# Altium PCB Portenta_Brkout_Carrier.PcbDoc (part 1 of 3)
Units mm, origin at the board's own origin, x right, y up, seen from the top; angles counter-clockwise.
Board outline 163.96 x 72.14 mm, 4 copper layers (Top, GND, PWR, Bottom), stack 1.612 mm thick; 71 components, 171 nets, 700 pads, 387 vias.
Unrouted connection lines stored in the file: 2.
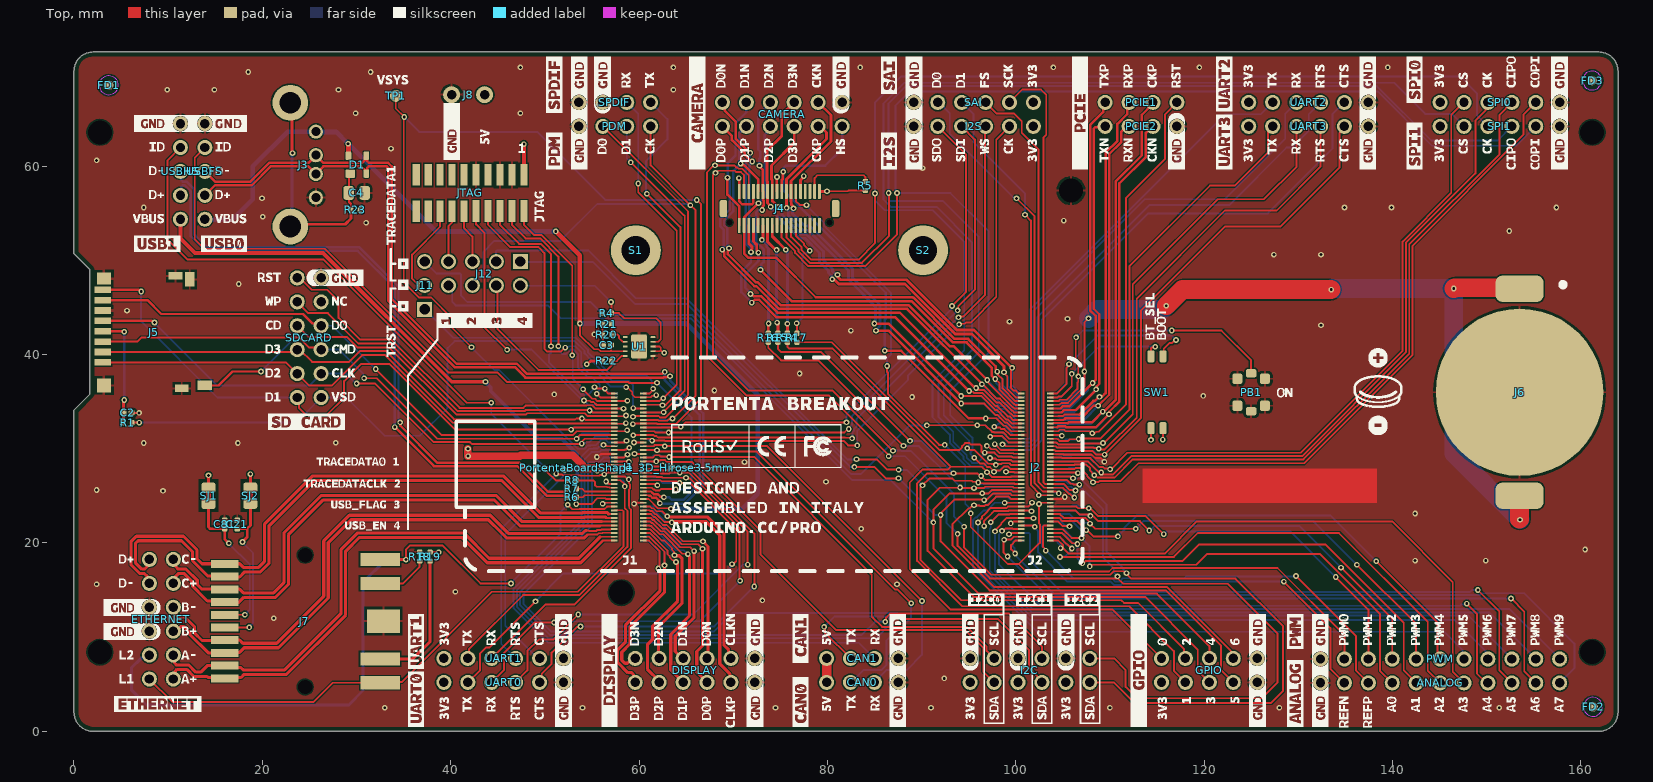
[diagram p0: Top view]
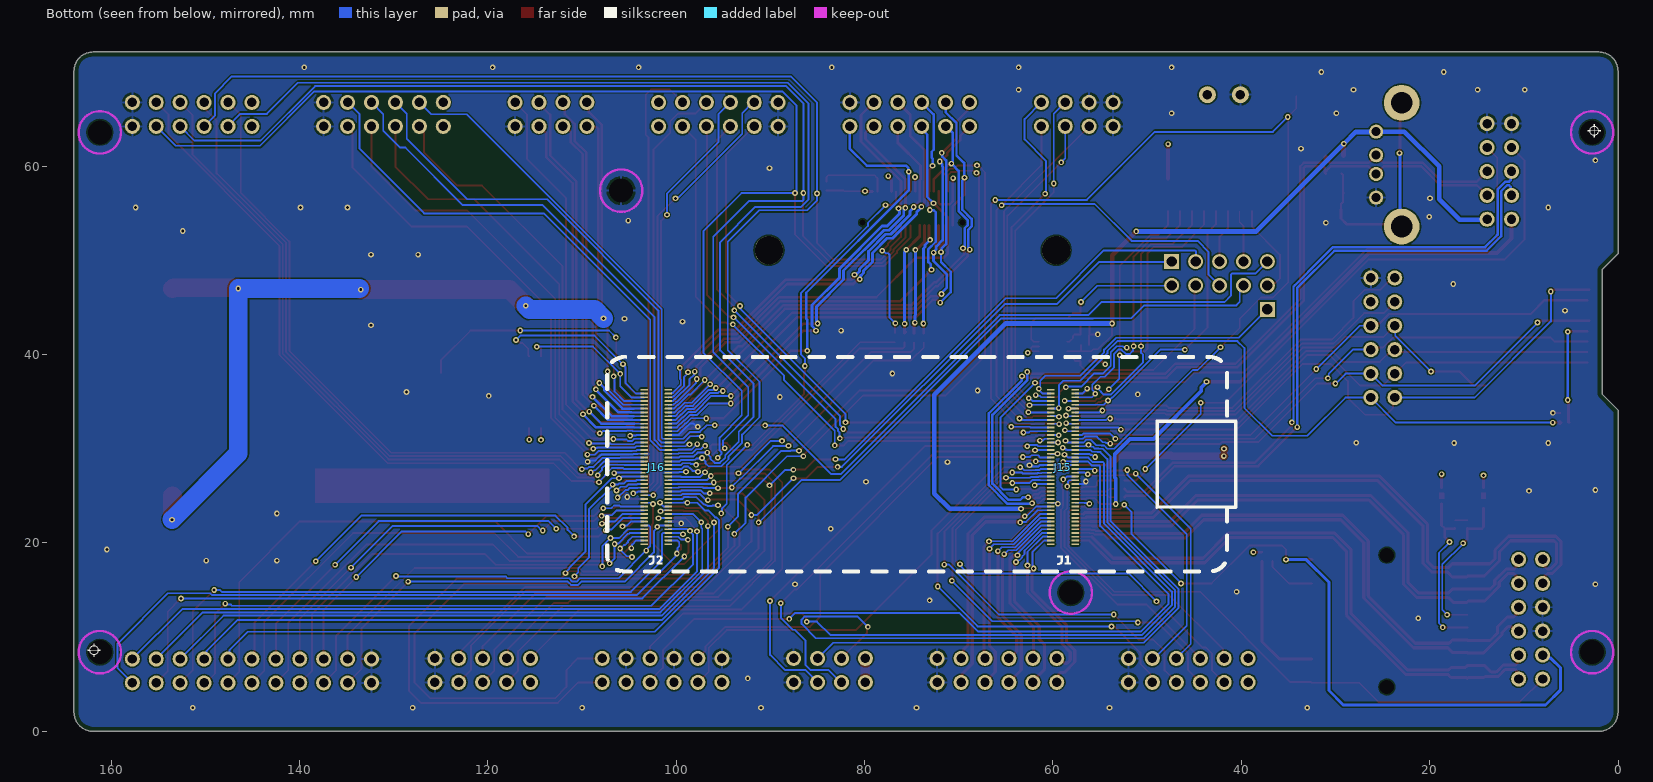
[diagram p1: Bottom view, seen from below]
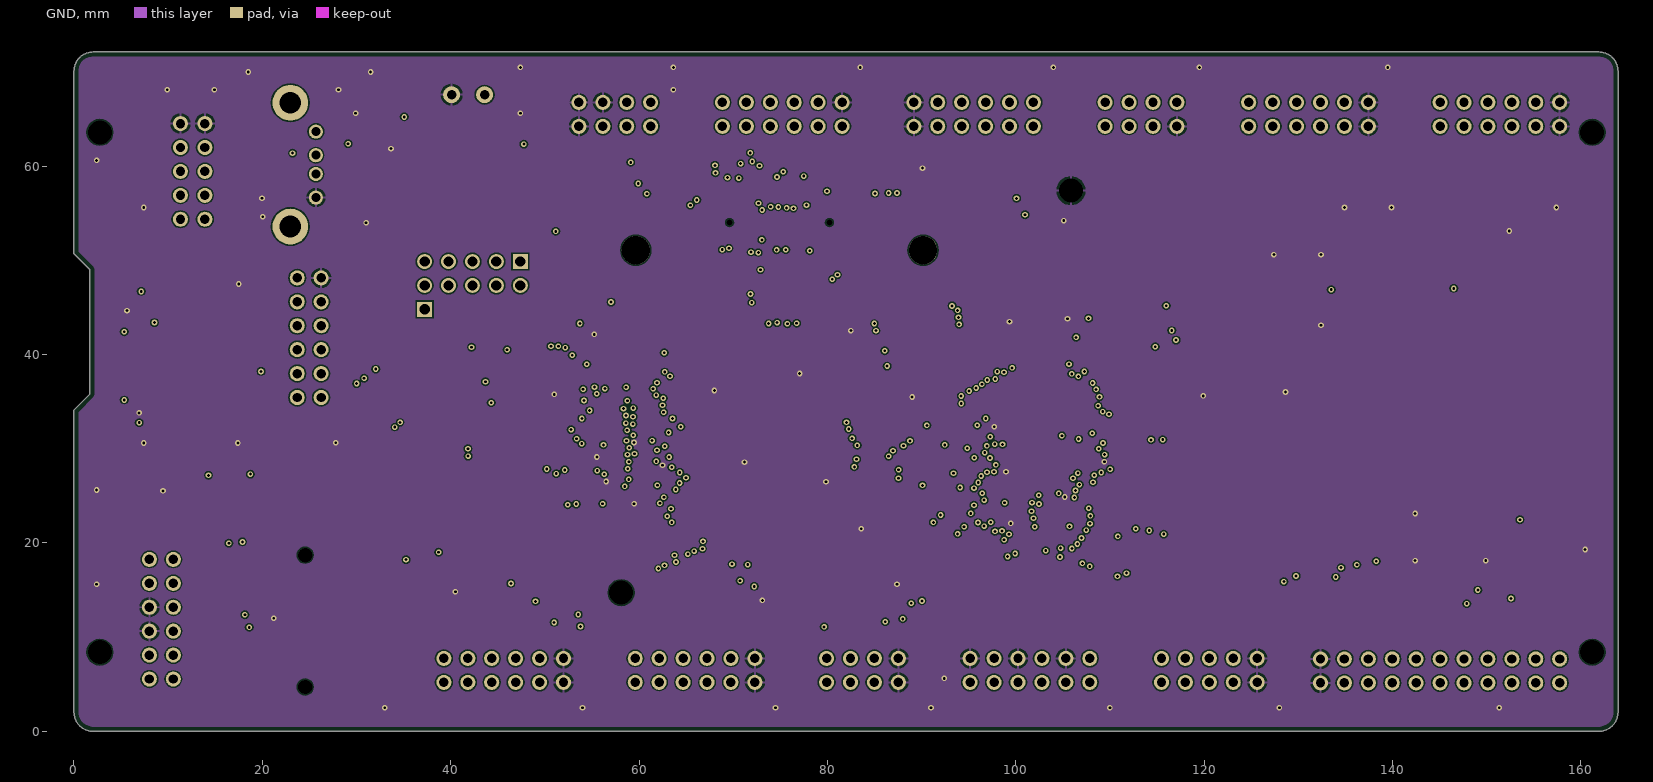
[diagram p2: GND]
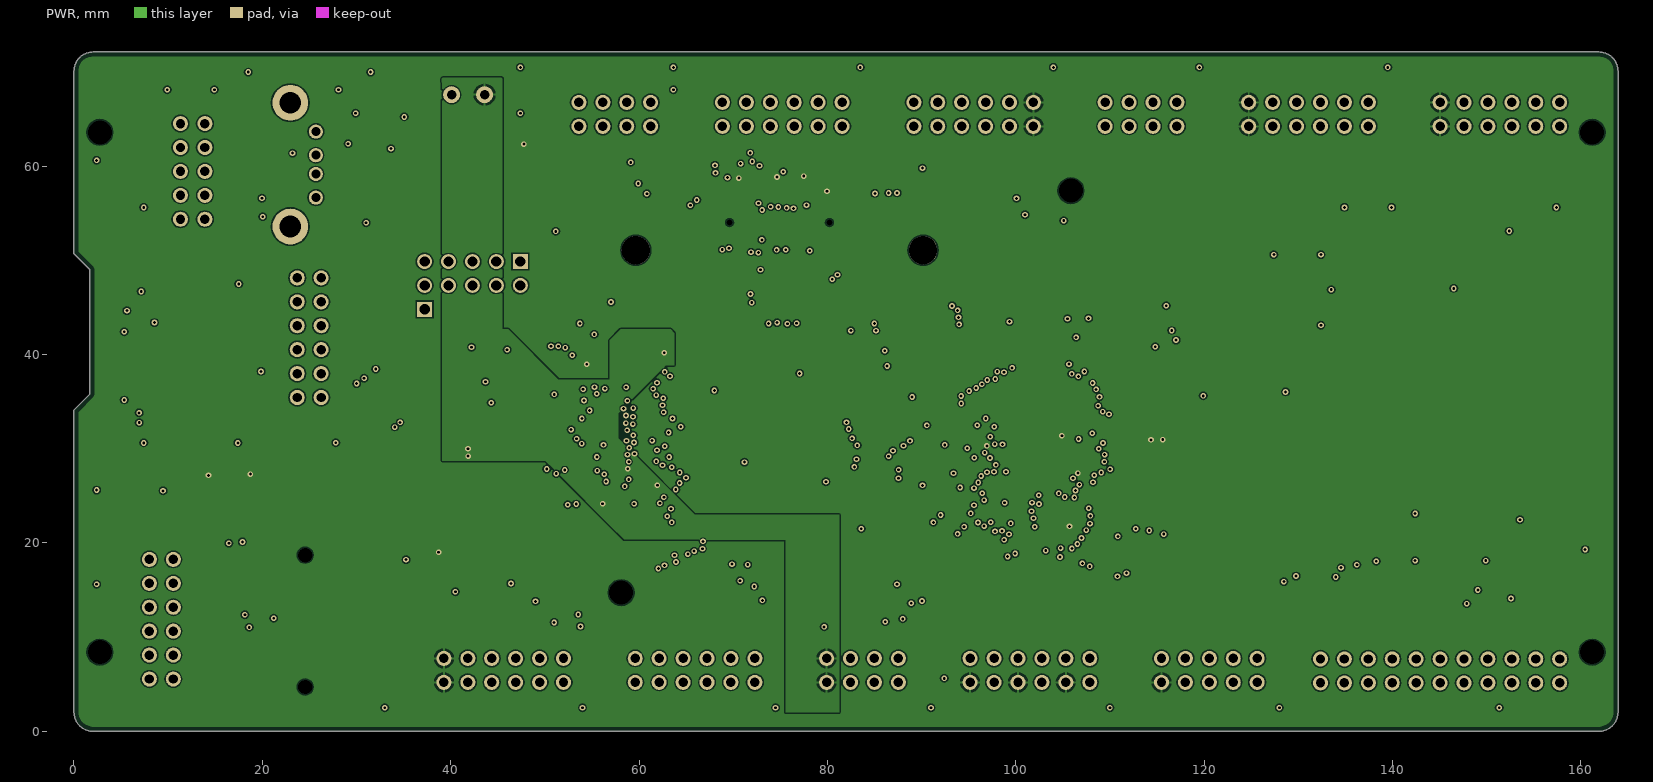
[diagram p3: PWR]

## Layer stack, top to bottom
Top Solder: solder mask 0.0102, Solder Resist, Dk 3.5
Top: signal copper 0.035
Dielectric 1: prepreg 0.356, FR-4, Dk 4.1
GND: signal copper 0.035
Dielectric3: core 0.76, FR-4, Dk 4.8
PWR: signal copper 0.035
Dielectric2: prepreg 0.356, FR-4, Dk 4.1
Bottom: signal copper 0.035
Bottom Solder: solder mask 0.0102, Solder Resist, Dk 3.5

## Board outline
0,2.032 0,34.11 1.7,35.81 1.7,49 0,50.7 0,70.104 cw(c2.032,70.104) 2.032,72.136 2.058,72.136 161.925,72.136 cw(c161.925,70.104) 163.957,70.104 163.957,70.078 163.957,2.032 cw(c161.925,2.032) 161.925,0 2.032,0 cw(c2.032,2.032)

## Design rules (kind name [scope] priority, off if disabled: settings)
BoardOutlineClearance mousebites [(ObjectKind = 'Pad') And (Name = 'Free-MOUSEBITES')] p1: gap=0 ignorepadtopadclearanceinfootprint=FALSE
BoardOutlineClearance [All] p2: gap=0.5 ignorepadtopadclearanceinfootprint=FALSE
Clearance Clearance_Diff [InAnyDifferentialPair] p1: gap=0.127 ignorepadtopadclearanceinfootprint=TRUE
Clearance [All] p2: gap=0.15 ignorepadtopadclearanceinfootprint=TRUE
DiffPairsRouting DiffPairsRouting_CAM [All] p1 off: maxlimit=0.254 minlimit=0.127 mostfreqgap=0.254 toplayer_prefgap=0.15 toplayer_minwidth=0.264 toplayer_maxwidth=0.381 toplayer_prefwidth=0.33 bottomlayer_prefgap=0.15 bottomlayer_minwidth=0.264 bottomlayer_maxwidth=0.381 bottomlayer_prefwidth=0.328 impedanceprofiledriven=TRUE impedanceprofileid={37DED0B3-47C4-494E-94CB-F43A59EAE40C} impedanceprofilevalue=100.000000 maxuncoupledlength=12.7
DiffPairsRouting DiffPairsRouting_DISPLAY [InDifferentialPairClass('DSI')] p2 off: maxlimit=0.254 minlimit=0.15 mostfreqgap=0.254 toplayer_prefgap=0.15 toplayer_minwidth=0.328 toplayer_maxwidth=0.381 toplayer_prefwidth=0.33 bottomlayer_prefgap=0.15 bottomlayer_minwidth=0.328 bottomlayer_maxwidth=0.381 bottomlayer_prefwidth=0.328 impedanceprofiledriven=TRUE impedanceprofileid={37DED0B3-47C4-494E-94CB-F43A59EAE40C} impedanceprofilevalue=100.000000 maxuncoupledlength=12.7
DiffPairsRouting DiffPairsRouting_USB [InDifferentialPairClass('USB')] p3: maxlimit=0.254 minlimit=0.127 mostfreqgap=0.254 toplayer_maxgap=0.127 toplayer_prefgap=0.127 toplayer_minwidth=0.2 toplayer_maxwidth=0.264 toplayer_prefwidth=0.264 bottomlayer_maxgap=0.127 bottomlayer_prefgap=0.127 bottomlayer_minwidth=0.264 bottomlayer_maxwidth=0.264 bottomlayer_prefwidth=0.264 impedanceprofiledriven=TRUE impedanceprofileid={A94ECF99-AB87-4BDF-9033-C085802CB064} impedanceprofilevalue=90.000000 maxuncoupledlength=12.7
DiffPairsRouting DiffPairsRouting_ETH [InDifferentialPairClass('ETH')] p4: maxlimit=0.254 minlimit=0.15 mostfreqgap=0.254 toplayer_maxgap=0.15 toplayer_prefgap=0.15 toplayer_minwidth=0.328 toplayer_maxwidth=0.33 toplayer_prefwidth=0.33 bottomlayer_maxgap=0.15 bottomlayer_prefgap=0.15 bottomlayer_minwidth=0.328 bottomlayer_maxwidth=0.328 bottomlayer_prefwidth=0.328 impedanceprofiledriven=TRUE impedanceprofileid={37DED0B3-47C4-494E-94CB-F43A59EAE40C} impedanceprofilevalue=100.000000 maxuncoupledlength=12.7
DiffPairsRouting DiffPairsRouting_PCIE [InDifferentialPairClass('PCIE')] p5: maxlimit=0.254 minlimit=0.127 mostfreqgap=0.254 toplayer_prefgap=0.127 toplayer_minwidth=0.264 toplayer_maxwidth=0.381 toplayer_prefwidth=0.264 bottomlayer_prefgap=0.127 bottomlayer_minwidth=0.264 bottomlayer_maxwidth=0.381 bottomlayer_prefwidth=0.264 impedanceprofiledriven=TRUE impedanceprofileid={A94ECF99-AB87-4BDF-9033-C085802CB064} impedanceprofilevalue=90.000000 maxuncoupledlength=12.7
HoleSize [All] p1: absolutevalues=TRUE maxlimit=5 minlimit=0.025 maxpercent=80.000 minpercent=20.000
MinimumSolderMaskSliver [All] p1 off: minsoldermaskwidth=0.254
PolygonConnect [All] p1: thpad.connectstyle=Relief thpad.reliefconductorwidth=0.254 thpad.reliefentries=4 thpad.polygonreliefangle="90 Angle" thpad.airgapwidth=0.254 smdpad.connectstyle=Relief smdpad.reliefconductorwidth=0.254 smdpad.reliefentries=4 smdpad.polygonreliefangle="90 Angle" smdpad.airgapwidth=0.254 via.connectstyle=Direct via.reliefconductorwidth=0.254 via.reliefentries=4 via.polygonreliefangle="90 Angle" via.airgapwidth=0.254
RoomDefinition "HDConnectors MALE" [InComponentClass('HDConnectors MALE')] p1 off: confinementstyle=ConfineIn formatcopy=TRUE lockcomponents=FALSE outline 165.1,0.381 173.99,0.381 173.99,20.193 165.1,20.193
RoomDefinition USB [InComponentClass('USB')] p2 off: confinementstyle=ConfineIn formatcopy=TRUE lockcomponents=FALSE outline 165.1,145.542 179.451,145.542 179.451,157.099 165.1,157.099
RoomDefinition U_ETHERNET [InComponentClass('U_ETHERNET')] p3 off: confinementstyle=ConfineIn formatcopy=TRUE lockcomponents=FALSE outline 165.1,119.761 217.551,119.761 217.551,145.415 165.1,145.415
RoomDefinition TOP [InComponentClass('TOP')] p4 off: confinementstyle=ConfineIn formatcopy=TRUE lockcomponents=FALSE outline 165.1,87.757 416.56,87.757 416.56,118.364 165.1,118.364
RoomDefinition SD [InComponentClass('SD')] p5 off: confinementstyle=ConfineIn formatcopy=TRUE lockcomponents=FALSE outline 165.1,69.977 197.485,69.977 197.485,87.63 165.1,87.63
RoomDefinition "HDConnectors FEMALE" [InComponentClass('HDConnectors FEMALE')] p6 off: confinementstyle=ConfineIn formatcopy=TRUE lockcomponents=FALSE outline 165.1,0.127 196.596,0.127 196.596,68.707 165.1,68.707
RoutingLayers [All] p1: top layer_v5=TRUE mid layer 1_v5=FALSE mid layer 2_v5=FALSE bottom layer_v5=TRUE
RoutingVias [All] p1: holewidth=0.3 width=0.6 viastyle="Through Hole" minholewidth=0.15 minwidth=0.3 maxholewidth=0.711 maxwidth=1.27
SMDEntry [All] p1: side=TRUE corner=FALSE anyangle=FALSE
SMDNeckDown [All] p1 off: percent=10.000
SolderMaskExpansion VIA [IsVia] p1: expansion=0.102 istentingtop=TRUE
SolderMaskExpansion [All] p2: expansion=0.1 istentingtop=FALSE
Width [All] p1: maxlimit=2 minlimit=0.127 preferedwidth=0.2
26 further rules are at their usual default settings.

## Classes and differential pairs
net class USB: D_1_N D_1_P
differential pair class USB: D_1 USB_FS.D_1 USB_HS.D_1
differential pair class PCIE: PCIE.CK_1 PCIE.RX_1 PCIE.TX_1
differential pair class ETH: ETH.A_1 ETH.B_1 ETH.C_1 ETH.D_1
differential pair class DSI: DISPLAY.CLK_1 DISPLAY.D0_1 DISPLAY.D1_1 DISPLAY.D2_1 DISPLAY.D3_1
differential pair class CAM: CAM.CK_1 CAM.D0_1 CAM.D1_1 CAM.D2_1 CAM.D3_1
component class "HDConnectors MALE": 2 J15 J16
component class USB: C3 C4 D1 J3 R4 R20 R21 R22 R23 U1
component class U_ETHERNET: C21 C81 J7 R18 R19 SJ1 SJ2
component class TOP: ANALOG CAMERA CAN0 CAN1 DISPLAY ETHERNET FD1 FD2 FD3 GPIO I2C I2S J4 J6 J8 J11 J12 JTAG PB1 PCIE1 PCIE2 PDM PWM R5 R6 R7 R8 R14 R15 R16 R17 S1 S2 SAI SDCARD SPDIF SPI0 SPI1 SW1 TP1 UART0 UART1 UART2 UART3 USBFS USBHS
component class SD: C2 J5 R1
component class "HDConnectors FEMALE": J1 J2 PortentaBoardShape_3D_Hirose3.5mm
differential pair D_1: +D_1_P -D_1_N
differential pair USB_HS.D_1: +USB_HS.D_1_P -USB_HS.D_1_N
differential pair USB_FS.D_1: +USB_FS.D_1_P -USB_FS.D_1_N
differential pair PCIE.TX_1: +PCIE.TX_1_P -PCIE.TX_1_N
differential pair PCIE.RX_1: +PCIE.RX_1_P -PCIE.RX_1_N
differential pair PCIE.CK_1: +PCIE.CK_1_P -PCIE.CK_1_N
differential pair ETH.D_1: +ETH.D_1_P -ETH.D_1_N
differential pair ETH.C_1: +ETH.C_1_P -ETH.C_1_N
differential pair ETH.B_1: +ETH.B_1_P -ETH.B_1_N
differential pair ETH.A_1: +ETH.A_1_P -ETH.A_1_N
differential pair DISPLAY.D3_1: +DISPLAY.D3_1_P -DISPLAY.D3_1_N
differential pair DISPLAY.D2_1: +DISPLAY.D2_1_P -DISPLAY.D2_1_N
differential pair DISPLAY.D1_1: +DISPLAY.D1_1_P -DISPLAY.D1_1_N
differential pair DISPLAY.D0_1: +DISPLAY.D0_1_P -DISPLAY.D0_1_N
differential pair DISPLAY.CLK_1: +DISPLAY.CLK_1_P -DISPLAY.CLK_1_N
differential pair CAM.D3_1: +CAM.D3_1_P -CAM.D3_1_N
differential pair CAM.D2_1: +CAM.D2_1_P -CAM.D2_1_N
differential pair CAM.D1_1: +CAM.D1_1_P -CAM.D1_1_N
differential pair CAM.D0_1: +CAM.D0_1_P -CAM.D0_1_N
differential pair CAM.CK_1: +CAM.CK_1_P -CAM.CK_1_N

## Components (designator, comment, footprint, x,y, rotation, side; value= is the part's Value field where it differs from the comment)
ANALOG "PIN HEADER 2.54mm VERT. 1x11POS" "PIN HEADER 2.54mm VERT. 1x11POS" 145.06,5.14 r180 top
C2 "C0402C104K3PACTU" CAP-0402 5.693,33.806 r180 top value=100nF
C3 "C0402C104K3PACTU" CAP-0402 56.594,41.002 r180 top value=100nF
C4 "C0805C472KDRACTU" CAP-0805 30.017,57.169 r180 top value=4.7nF
C21 "C0402C104K3PACTU" CAP-0402 17.335,21.971 r90 top value=100nF
C81 "C0402C104K3PACTU" CAP-0402 16.005,21.971 r90 top value=100nF
CAMERA "PIN HEADER 2.54mm VERT. 2x6POS" "PIN HEADER 2.54mm VERT. 2x6POS" 75.21,65.51 r180 top
CAN0 "PIN HEADER 2.54mm VERT. 1x4POS" "PIN HEADER 2.54mm VERT. 1x4POS-Footprint-1" 83.73,5.2 r0 top
CAN1 "PIN HEADER 2.54mm VERT. 1x4POS" "PIN HEADER 2.54mm VERT. 1x4POS-Footprint-1" 83.73,7.74 r0 top
D1 "PRTR5V0U2X,215" SOT190P230X110-4N 30.096,60.17 r0 top
DISPLAY "PIN HEADER 2.54mm VERT. 2x6POS" "PIN HEADER 2.54mm VERT. 2x6POS" 65.95,6.47 r0 top
ETHERNET "PIN HEADER 2.54mm VERT. 2x6POS" "PIN HEADER 2.54mm VERT. 2x6POS" 9.28,11.9 r90 top
FD1 "Fiducial mark 1.5mm" FIDUCIAL-1.5 3.7,68.6 r0 top
FD2 "Fiducial mark 1.5mm" FIDUCIAL-1.5 161.3,2.6 r0 top
FD3 "Fiducial mark 1.5mm" FIDUCIAL-1.5 161.2,69.1 r0 top
GPIO "PIN HEADER 2.54mm VERT. 2x5POS" "PIN HEADER 2.54mm VERT. 2x5POS" 120.56,6.47 r0 top
I2C "PIN HEADER 2.54mm VERT. 2x6POS" "PIN HEADER 2.54mm VERT. 2x6POS" 101.51,6.47 r0 top
I2S "PIN HEADER 2.54mm VERT. 1x6POS" "PIN HEADER 2.54mm VERT. 1x6POS" 95.53,64.24 r180 top
J1 "DF40HC(3.5)-80DS-0.4V(51)-LEFT" DF40HC(3.5)-80DS-0.4V(51)-Footprint-1 58.93,28.064 r90 top locked
J2 "DF40HC(3.5)-80DS-0.4V(51)-RIGHT" DF40HC(3.5)-80DS-0.4V(51)-Footprint-1 102.11,28.064 r270 top locked
J3 "20TW-594" 20TW595-Footprint-1 24.334,60.17 r270 top
J4 "DF12(3.0)-36DS-0.5V(86)" DF12(3.0)-36DS-0.5V(86)-Footprint-1 74.9,55.524 r180 top locked
J5 "114-00841-68" AMPHENOL_114-00841-68 8.962,42.38 r270 top
J6 "BK-912-TR" MPD-CN-DIN-3_V 153.5,36 r270 top
J7 "MTJ-88AX1-FS-TSMT-P-L5-M398AC-WOT-K" MTJ-88AX1-FS-TSMT-P-L5-M398AC-WOT-K-Footprint-1 24.68,11.7 r270 top locked
J8 "MK125002GO" MK125002GO 41.85,67.6 r180 top
J11 "61300311121" 61300311121 35.964,43.531 r90 top
J12 "10129381-908002BLF" 61300211121 43.584,48.611 r270 top
J15 "DF40C-80DP-0.4V(51)-LEFT" DF40C-80DP-0.4V(51)-Footprint-1 58.94,28.064 r90 bottom locked
J16 "DF40C-80DP-0.4V(51)-RIGHT" DF40C-80DP-0.4V(51)-Footprint-1 102.12,28.064 r270 bottom
JTAG "FTSH-110-01-F-DV" FTSH-105-01-F-DV-Footprint-1 42.059,57.19 r180 top
PB1 "PTS820J25KSMTRLFS" C&K_PTS820_NO_HOLES-1 125,36 r90 top
PCIE1 "PIN HEADER 2.54mm VERT. 1x4POS" "PIN HEADER 2.54mm VERT. 1x4POS-Footprint-1" 113.31,66.78 r0 top
PCIE2 "PIN HEADER 2.54mm VERT. 1x4POS" "PIN HEADER 2.54mm VERT. 1x4POS-Footprint-1" 113.31,64.24 r0 top
PDM "PIN HEADER 2.54mm VERT. 1x4POS" "PIN HEADER 2.54mm VERT. 1x4POS-Footprint-1" 57.43,64.24 r180 top
PortentaBoardShape_3D_Hirose3.5mm "PortentaBoardShape_3D_Hirose3.5mm" PortentaBoardShape3D-Footprint-1 58.718,27.996 r0 top locked
PWM "PIN HEADER 2.54mm VERT. 1x11POS" "PIN HEADER 2.54mm VERT. 1x11POS" 145.06,7.68 r180 top
R1 "CRCW04020000Z0EDC" RES-0402#1 5.7,32.775 r180 top value=0
R4 "CRCW0402100KFKEDC" RES-0402#1 56.594,44.413 r180 top value=100k
R5 "CRCW04020000Z0EDC" RES-0402#2 84.038,57.909 r90 top value=0
R6 "CRCW04020000Z0EDC" RES-0402#1 52.875,24.85 r0 top value=0
R7 "CRCW04020000Z0EDC" RES-0402#1 52.882,25.758 r0 top value=0
R8 "CRCW04020000Z0EDC" RES-0402#1 52.9,26.65 r0 top value=0
R14 "CRCW04020000Z0EDC" RES-0402#1 75.757,41.789 r270 top value=0
R15 "CRCW04020000Z0EDC" RES-0402#1 74.741,41.789 r270 top value=0
R16 "CRCW04020000Z0EDC" RES-0402#1 73.725,41.789 r270 top value=0
R17 "CRCW04020000Z0EDC" RES-0402#1 76.773,41.789 r270 top value=0
R18 "CRCW0402470RJNED" RES-0402#1 36.71,18.55 r90 top value=470
R19 "CRCW0402470RJNED" RES-0402#1 37.81,18.55 r90 top value=470
R20 "CRCW0402100KFKEDC" RES-0402#1 56.594,42.125 r180 top value=100k
R21 "CRCW0402100KFKEDC" RES-0402#1 56.594,43.248 r180 top value=100k
R22 "CRCW0402100KFKEDC" RES-0402#1 56.594,39.329 r0 top value=100k
R23 "CRCW04021M00FKED" RES-0402#1 29.89,55.391 r180 top value=1M
S1 "9774030243R" 9774030243R-Footprint-1 59.664,51.081 r0 top
S2 "9774030243R" 9774030243R-Footprint-1 90.164,51.081 r0 top
SAI "PIN HEADER 2.54mm VERT. 1x6POS" "PIN HEADER 2.54mm VERT. 1x6POS" 95.53,66.78 r180 top
SDCARD "PIN HEADER 2.54mm VERT. 2x6POS" "PIN HEADER 2.54mm VERT. 2x6POS" 24.98,41.794 r90 top
SJ1 "SMD solder JUMPER CLOSED" SJ 14.287,25.019 r90 top net-tie
SJ2 "SMD solder JUMPER CLOSED" SJ 18.732,25.019 r90 top net-tie
SPDIF "PIN HEADER 2.54mm VERT. 1x4POS" "PIN HEADER 2.54mm VERT. 1x4POS-Footprint-1" 57.43,66.78 r180 top
SPI0 "PIN HEADER 2.54mm VERT. 1x6POS" "PIN HEADER 2.54mm VERT. 1x6POS" 151.41,66.78 r0 top
SPI1 "PIN HEADER 2.54mm VERT. 1x6POS" "PIN HEADER 2.54mm VERT. 1x6POS" 151.41,64.24 r0 top
SW1 "218-2LPSTRF" CTS-218-2LPST_V 115,36 r90 top
TP1 "CMP-018-0006-A.4" TP-1.27MM 34.175,67.471 r0 top
U1 "NCP383LMUAJAATXG" PQFN50P300X300X55_HS-21L 60.009,40.858 r90 top
UART0 "PIN HEADER 2.54mm VERT. 1x6POS" "PIN HEADER 2.54mm VERT. 1x6POS" 45.63,5.2 r0 top
UART1 "PIN HEADER 2.54mm VERT. 1x6POS" "PIN HEADER 2.54mm VERT. 1x6POS" 45.63,7.74 r0 top locked
UART2 "PIN HEADER 2.54mm VERT. 1x6POS" "PIN HEADER 2.54mm VERT. 1x6POS" 131.09,66.78 r0 top
UART3 "PIN HEADER 2.54mm VERT. 1x6POS" "PIN HEADER 2.54mm VERT. 1x6POS" 131.09,64.24 r0 top
USBFS "PIN HEADER 2.54mm VERT. 1x5POS" "PIN HEADER 2.54mm VERT. 1x5POS" 13.91,59.45 r90 top
USBHS "PIN HEADER 2.54mm VERT. 1x5POS" "PIN HEADER 2.54mm VERT. 1x5POS" 11.31,59.45 r90 top

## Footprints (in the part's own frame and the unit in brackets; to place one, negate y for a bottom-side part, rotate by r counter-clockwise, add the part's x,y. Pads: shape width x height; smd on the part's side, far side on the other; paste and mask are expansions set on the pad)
20TW595-Footprint-1 [mm]
  round 1.5 hole 0.95: 1(-3.5,1.355) 2(-1,1.355) 3(1,1.355) 4(3.5,1.355)
  round 3.8 hole 2.3: 5(-6.57,-1.355) 6(6.57,-1.355)
  body extent -7.9,-3.35 7.9,3.65, height 15.05
9774030243R-Footprint-1 [mm]
  round 5.3 smd paste-6: 2(0,0)
  round 3 hole 3 unplated: ""(0,0)
61300211121 [mm] "Pin Header, pitch 2.54 mm, THT, Vertical, single row, 2p"
  rect 1.6x1.6 hole 1.1: 1(-1.27,3.81)
  round 1.6 hole 1.1: 2(1.27,3.81) 3(-1.27,1.27) 4(1.27,1.27) 5(-1.27,-1.27) 6(1.27,-1.27) 7(-1.27,-3.81) 8(1.27,-3.81)
  body extent -2.54,-5.08 2.54,5.08, height 8.57
61300311121 [mm] "Pin Header, pitch 2.54 mm, THT, Vertical, single row, 3p"
  rect 1.6x1.6 hole 1.1: 1(1.27,-1.27)
  round 1.6 hole 1.1: 2(3.81,-1.27) 3(6.35,-1.27)
  body extent 0,-2.54 7.62,0, height 8.57
AMPHENOL_114-00841-68 [mm]
  rect 0.7x1.75 smd: 1(3.2,-5.888) 2(2.1,-5.888) 3(1,-5.888) 4(-0.1,-5.888) 5(-1.2,-5.888) 6(-2.3,-5.888) 7(-3.4,-5.888) 8(-4.5,-5.888)
  rect 1x1.55 smd: CD1(5.65,4.912)
  rect 1.55x1 smd: CD2(-5.602,3.337)
  rect 1.3x1.5 smd: SH1(-5.7,-5.76)
  rect 1.5x1.5 smd: SH2(5.65,-5.76)
  rect 0.8x1.4 smd: SH3(5.975,2.487)
  rect 0.8x1.5 smd: SH4(-5.975,1.837)
  body extent -6,-10.29 6,4.99, height 1.6
C&K_PTS820_NO_HOLES-1 [mm]
  rrect49% 0.89x1.12 smd: 5(-2.015,0) 6(2.015,0)
  rrect46% 1.11x1.09 smd: PAD(-1.434,-1.46) PAD(-1.434,1.46) PAD(1.434,-1.46) PAD(1.434,1.46)
  body extent -2.25,-1.45 2.25,1.45, height 2
CAP-0402 [mm] "Chip Capacitor, 2-Leads, Body  0402 (in) 1005 (mm), IPC Medium Density"
  rrect52% 0.63x0.58 smd mask+0: 1(-0.435,0) 2(0.435,0)
  body extent -0.5,-0.25 0.5,0.25, height 0.5
CAP-0805 [mm] "Chip Capacitor, Body 0805 imperial, 2.0x1.2mm, IPC Medium Density"
  rrect45% 1.11x1.47 smd mask+0: 1(-0.85,0) 2(0.85,0)
  body extent -1,-0.62 1,0.63, height 1.25
CTS-218-2LPST_V [mm] "SMD, 4-Leads, Body 5.8x3.71mm, Pitch 1.27mm"
  rrect50% 1.27x0.76 smd: 1(-3.81,0.635) 2(-3.81,-0.635) 3(3.81,-0.635) 4(3.81,0.635)
  body extent -2.9,-1.86 2.9,1.86, height 2.65
DF12(3.0)-36DS-0.5V(86)-Footprint-1 [mm]
  rrect50% 0.3x1.6 smd: 1(-4.25,1.8) 2(-4.25,-1.8) 3(-3.75,1.8) 4(-3.75,-1.8) 5(-3.25,1.8) 6(-3.25,-1.8) 7(-2.75,1.8) 8(-2.75,-1.8) 9(-2.25,1.8) 10(-2.25,-1.8) 11(-1.75,1.8) 12(-1.75,-1.8) 13(-1.25,1.8) 14(-1.25,-1.8) 15(-0.75,1.8) 16(-0.75,-1.8) 17(-0.25,1.8) 18(-0.25,-1.8) 19(0.25,1.8) 20(0.25,-1.8) 21(0.75,1.8) 22(0.75,-1.8) 23(1.25,1.8) 24(1.25,-1.8) 25(1.75,1.8) 26(1.75,-1.8) 27(2.25,1.8) 28(2.25,-1.8) 29(2.75,1.8) 30(2.75,-1.8) 31(3.25,1.8) 32(3.25,-1.8) 33(3.75,1.8) 34(3.75,-1.8) 35(4.25,1.8) 36(4.25,-1.8)
  rrect50% 0.325x0.325 hole 0.65 unplated: MH1(-5.318,1.514) MH2(5.282,1.514)
  rrect50% 0.8x1.8 smd: MP1(-5.968,0.014) MP2(5.932,0.014)
  body extent -6.29,-2.56 6.25,2.58, height 2.5
DF40C-80DP-0.4V(51)-Footprint-1 [mm]
  rrect53% 0.19x0.8 smd paste+0 mask+0: 1(-7.8,-1.29) 2(-7.8,1.29) 3(-7.4,-1.29) 4(-7.4,1.29) 5(-7,-1.29) 6(-7,1.29) 7(-6.6,-1.29) 8(-6.6,1.29) 9(-6.2,-1.29) 10(-6.2,1.29) 11(-5.8,-1.29) 12(-5.8,1.29) 13(-5.4,-1.29) 14(-5.4,1.29) 15(-5,-1.29) 16(-5,1.29) 17(-4.6,-1.29) 18(-4.6,1.29) 19(-4.2,-1.29) 20(-4.2,1.29) 21(-3.8,-1.29) 22(-3.8,1.29) 23(-3.4,-1.29) 24(-3.4,1.29) 25(-3,-1.29) 26(-3,1.29) 27(-2.6,-1.29) 28(-2.6,1.29) 29(-2.2,-1.29) 30(-2.2,1.29) 31(-1.8,-1.29) 32(-1.8,1.29) 33(-1.4,-1.29) 34(-1.4,1.29) 35(-1,-1.29) 36(-1,1.29) 37(-0.6,-1.29) 38(-0.6,1.29) 39(-0.2,-1.29) 40(-0.2,1.29) 41(0.2,-1.29) 42(0.2,1.29) 43(0.6,-1.29) 44(0.6,1.29) 45(1,-1.29) 46(1,1.29) 47(1.4,-1.29) 48(1.4,1.29) 49(1.8,-1.29) 50(1.8,1.29) 51(2.2,-1.29) 52(2.2,1.29) 53(2.6,-1.29) 54(2.6,1.29) 55(3,-1.29) 56(3,1.29) 57(3.4,-1.29) 58(3.4,1.29) 59(3.8,-1.29) 60(3.8,1.29) 61(4.2,-1.29) 62(4.2,1.29) 63(4.6,-1.29) 64(4.6,1.29) 65(5,-1.29) 66(5,1.29) 67(5.4,-1.29) 68(5.4,1.29) 69(5.8,-1.29) 70(5.8,1.29) 71(6.2,-1.29) 72(6.2,1.29) 73(6.6,-1.29) 74(6.6,1.29) 75(7,-1.29) 76(7,1.29) 77(7.4,-1.29) 78(7.4,1.29) 79(7.8,-1.29) 80(7.8,1.29) M1(-8.2,-1.29) M2(8.2,-1.29) M3(8.2,1.29) M4(-8.2,1.29)
  body extent -8.76,-1.48 8.76,1.49, height 1.14
DF40HC(3.5)-80DS-0.4V(51)-Footprint-1 [mm]
  rect 0.2x0.7 smd: 1(-7.8,1.54) 2(-7.8,-1.54) 3(-7.4,1.54) 4(-7.4,-1.54) 5(-7,1.54) 6(-7,-1.54) 7(-6.6,1.54) 8(-6.6,-1.54) 9(-6.2,1.54) 10(-6.2,-1.54) 11(-5.8,1.54) 12(-5.8,-1.54) 13(-5.4,1.54) 14(-5.4,-1.54) 15(-5,1.54) 16(-5,-1.54) 17(-4.6,1.54) 18(-4.6,-1.54) 19(-4.2,1.54) 20(-4.2,-1.54) 21(-3.8,1.54) 22(-3.8,-1.54) 23(-3.4,1.54) 24(-3.4,-1.54) 25(-3,1.54) 26(-3,-1.54) 27(-2.6,1.54) 28(-2.6,-1.54) 29(-2.2,1.54) 30(-2.2,-1.54) 31(-1.8,1.54) 32(-1.8,-1.54) 33(-1.4,1.54) 34(-1.4,-1.54) 35(-1,1.54) 36(-1,-1.54) 37(-0.6,1.54) 38(-0.6,-1.54) 39(-0.2,1.54) 40(-0.2,-1.54) 41(0.2,1.54) 42(0.2,-1.54) 43(0.6,1.54) 44(0.6,-1.54) 45(1,1.54) 46(1,-1.54) 47(1.4,1.54) 48(1.4,-1.54) 49(1.8,1.54) 50(1.8,-1.54) 51(2.2,1.54) 52(2.2,-1.54) 53(2.6,1.54) 54(2.6,-1.54) 55(3,1.54) 56(3,-1.54) 57(3.4,1.54) 58(3.4,-1.54) 59(3.8,1.54) 60(3.8,-1.54) 61(4.2,1.54) 62(4.2,-1.54) 63(4.6,1.54) 64(4.6,-1.54) 65(5,1.54) 66(5,-1.54) 67(5.4,1.54) 68(5.4,-1.54) 69(5.8,1.54) 70(5.8,-1.54) 71(6.2,1.54) 72(6.2,-1.54) 73(6.6,1.54) 74(6.6,-1.54) 75(7,1.54) 76(7,-1.54) 77(7.4,1.54) 78(7.4,-1.54) 79(7.8,1.54) 80(7.8,-1.54)
  body extent -9.32,-1.69 9.29,1.69, height 3.4
FIDUCIAL-1.5 [mil]
  rrect100% 40x40 smd paste-100: 1(0,0)
  Top keep-out circle w5: c0,0 r39.37
FTSH-105-01-F-DV-Footprint-1 [mm]
  rect 0.76x2.3 smd: 1(-5.715,-1.9) 2(-5.715,1.95) 3(-4.445,-1.9) 4(-4.445,1.95) 5(-3.175,-1.9) 6(-3.175,1.95) 7(-1.905,-1.9) 8(-1.905,1.95) 9(-0.635,-1.9) 10(-0.635,1.95) 11(0.635,-1.896) 12(0.635,1.954) 13(1.905,-1.896) 14(1.905,1.954) 15(3.175,-1.896) 16(3.175,1.954) 17(4.445,-1.896) 18(4.445,1.954) 19(5.715,-1.896) 20(5.715,1.954)
  body extent -6.35,-2.9 6.35,2.95, height 6.06
MK125002GO [mm]
  round 1.8 hole 1: 1(-1.75,0) 2(1.75,0)
  body extent -3.95,-3.75 4.05,3.25, height 8.31
MPD-CN-DIN-3_V [mm] "CN-DIN, 3-Leads, Body 21.08x15.24mm"
  rrect50% 2.79x5.08 smd: 1(-10.985,0) 2(10.985,0)
  round 17.78 smd paste-18 mask+1: 3(0,0)
  silkscreen extent -11.68,4.36 -11.18,4.86, body extent -10.54,-10 10.57,10, height 4.57
MTJ-88AX1-FS-TSMT-P-L5-M398AC-WOT-K-Footprint-1 [mm]
  rect 1.4x4.2 smd: L1(6.55,7.825) L2(4.01,7.825) L3(-4.01,7.825) L4(-6.55,7.825)
  rect 0.85x2.9 smd: P1(6.075,-8.675) P2(4.725,-8.675) P3(3.375,-8.675) P4(2.025,-8.675) P5(0.675,-8.675) P6(-0.675,-8.675) P7(-2.025,-8.675) P8(-3.375,-8.675) P9(-4.725,-8.675) P10(-6.075,-8.675)
  round 0 hole 1.5 unplated: S1(-7,-0.125) S2(7,-0.125)
  rect 2.5x3.5 smd: S3(0,8.175)
  body extent -8.1,-9.88 8.1,9.62, height 16.85
"PIN HEADER 2.54mm VERT. 1x4POS-Footprint-1" [mm]
  round 1.6 hole 1: 1(-3.81,0) 2(-1.27,0) 3(1.27,0) 4(3.81,0)
"PIN HEADER 2.54mm VERT. 1x5POS" [mm]
  round 1.6 hole 1: 1(-5.08,0) 2(-2.54,0) 3(0,0) 4(2.54,0) 5(5.08,0)
"PIN HEADER 2.54mm VERT. 1x6POS" [mm]
  round 1.6 hole 1: 1(-6.35,0) 2(-3.81,0) 3(-1.27,0) 4(1.27,0) 5(3.81,0) 6(6.35,0)
"PIN HEADER 2.54mm VERT. 1x11POS" [mm]
  round 1.6 hole 1: 1(-12.7,0) 2(-10.16,0) 3(-7.62,0) 4(-5.08,0) 5(-2.54,0) 6(0,0) 7(2.54,0) 8(5.08,0) 9(7.62,0) 10(10.16,0) 11(12.7,0)
"PIN HEADER 2.54mm VERT. 2x5POS" [mm]
  round 1.6 hole 1: 1(-5.08,-1.27) 2(-5.08,1.27) 3(-2.54,-1.27) 4(-2.54,1.27) 5(0,-1.27) 6(0,1.27) 7(2.54,-1.27) 8(2.54,1.27) 9(5.08,-1.27) 10(5.08,1.27)
"PIN HEADER 2.54mm VERT. 2x6POS" [mm]
  round 1.6 hole 1: 1(-6.35,-1.27) 2(-6.35,1.27) 3(-3.81,-1.27) 4(-3.81,1.27) 5(-1.27,-1.27) 6(-1.27,1.27) 7(1.27,-1.27) 8(1.27,1.27) 9(3.81,-1.27) 10(3.81,1.27) 11(6.35,-1.27) 12(6.35,1.27)
PortentaBoardShape3D-Footprint-1 [mm]
  body extent -17.94,-12.7 48.9,12.7, height 8.29
PQFN50P300X300X55_HS-21L [mm] "PQFN, 20-Leads, Body 3.00x3.00mm, Pitch 0.50mm, Thermal Pad 1.69x2.59mm, IPC High Density"
  rrect50% 0.2x0.5 smd: 1(-1,-1.475) 2(-0.5,-1.475) 3(0,-1.475) 4(0.5,-1.475) 5(1,-1.475) 6(1,1.475) 7(0.5,1.475) 8(0,1.475) 9(-0.5,1.475) 10(-1,1.475)
  rrect25% 2.59x1.69 smd: 11(0,0)
  body extent -1.5,-1.5 1.5,1.5, height 0.55
RES-0402#1 [mm] "Chip Resistor, 2-Leads, Body  0402 (in) 1005 (mm), IPC Medium Density"
  rrect51% 0.55x0.58 smd mask+0: 1(-0.475,0) 2(0.475,0)
  body extent -0.5,-0.25 0.5,0.25, height 0.34
RES-0402#2 [mm] "Chip Resistor, 2-Leads, Body  0402 (in) 1005 (mm), IPC Medium Density"
  rrect51% 0.55x0.58 smd: 1(-0.475,0) 2(0.475,0)
  body extent -0.5,-0.25 0.5,0.25, height 0.34
SJ [mm]
  rrect45% 1.11x1.47 smd mask+0: 1(-0.85,0) 2(0.85,0)
  Top region: -0.31,0.254 -0.31,-0.254 0.31,-0.254 0.31,0.254
SOT190P230X110-4N [mm]
  rrect33% 1.01x0.91 smd paste+0 mask+0: 1(-0.75,-0.955)
  rrect49% 0.61x0.91 smd paste+0 mask+0: 2(0.95,-0.955) 3(0.95,0.955) 4(-0.95,0.955)
  body extent -1.45,-1.15 1.45,1.15, height 1
TP-1.27MM [mm]
  rrect100% 1.27x1.27 smd paste-2.54: X(0,0)

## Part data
ANALOG PWM: library part J0170-A.1
C2 C3 C21 C81: library part C0014-A.9, "CAP CHIP 0402 100nF 25V X5R 10%", Case Code (Imperial)=0402, Case Code (Metric)=1005, Dielectric=X5R, Manufacturer=KEMET, Manufacturer 2=AVX, Manufacturer Part Number 2=04023D104KAT2A, Tolerance=10%, Voltage=25V
C4: library part C0059-A.9, "CAP CHIP 0805 4.7nF 1000V X7R 10%", Case Code (Imperial)=0805, Case Code (Metric)=2012, Dielectric=X7R, Manufacturer=KEMET, Tolerance=10%, Voltage=1kV
CAMERA DISPLAY ETHERNET I2C SDCARD: library part J0165-A.1
CAN0: library part J0162-A.3
CAN1 PCIE1 PCIE2 PDM SPDIF: library part J0162-A.2
D1: library part D0025-A.3, "TVS ARRAY 4LIN.8kV 1pF SOT143B", Manufacturer=Nexperia
FD1 FD2 FD3: library part UT0000-A.3
GPIO: library part J0166-A.1
I2S SAI SPI0 SPI1 UART0 UART1 UART2 UART3: library part J0167-A.1
J1: library part J0016-A.10, "CONN RCPT FEMALE D80POS 0.4MM SMD GOLD", Current Rating=300mA, Manufacturer=Hirose, Package Quantity=1, Part Number=DF40HC(3.5)-80DS-0.4V(51), Voltage Rating=30V
J2: library part J0153-A.2, "CONN RCPT FEMALE D80POS 0.4MM SMD GOLD", Current Rating=300mA, Manufacturer=Hirose, Package Quantity=1, Part Number=DF40HC(3.5)-80DS-0.4V(51), Voltage Rating=30V
J3: library part J0135-A.4, "CONN USB A VERTICAL", Manufacturer=4UCON
J4: library part J0177-A.2, "CONN RCPT 36POS SMD GOLD H3.0mm", Contact Resistance=50mR, Dielectric Withstanding Voltage (AC)=150V, Flammability Rating="UL94 V-0", Insulation Color=Beige, Insulation Resistance=500MR, Manufacturer=Hirose, Max Operating Temperature=125°C, Min Operating Temperature=-45°C, Rated Current (Signal)=300mA
J5: library part J0011-A.3, "CONN Micro SD", Manufacturer=Amphenol
J6: library part J0072-A.3, "BATTERY RETAINER COIN 20MM SMD", Manufacturer="Memory Protection Devices"
J7: library part J0133-A.6, "CONN ETHERNET 1GIGABIT VERTICAL", Manufacturer="Adam Tech"
J8: library part J0012-A.4, "CONN MORS.CS 2v p3,5 10A aLING.VER", Manufacturer=Adimpex
J11: library part J0184-A.4, "CONN HEADER VERT 3POS 2.54MM", Contact Resistance=20mR, Insulation Color=Black, Insulation Resistance=1GR, Manufacturer 2=4UCON, Manufacturer Part Number 2=21TW-204, Max Operating Temperature=125°C, Min Operating Temperature=-40°C
J12: library part J0195-A.2, "CONN HEADER VERT 2x4 8POS 2.54MM", Color=Black, Contact Resistance=20mR, Current Rating=3A, Insulation Resistance=1GR, Manufacturer="Wurth Electronics", Manufacturer 2="Amphenol FCI", Max Operating Temperature=105°C, Min Operating Temperature=-55°C, Voltage Rating=250V
J15: library part J0015-A.8, "CONN HDR 80POS 0.4MM MALE SMD GOLD", Manufacturer=Hirose, Part Number=DF40C-80DP-0.4V(51)
J16: library part J0152-A.3, "CONN HDR 80POS 0.4MM MALE SMD GOLD", Manufacturer=Hirose, Part Number=DF40C-80DP-0.4V(51)
JTAG: library part J0203-A.1, "CONN HEADER SMD 20POS 2x10 1.27MM JTAG", Color=Black, Current Rating=1.75A, Manufacturer=Samtec, Manufacturer 2=4UCON, Manufacturer Part Number 2=22TW-056, Max Operating Temperature=125°C, Min Operating Temperature=-55°C, Package Quantity=1
PB1: library part B0006-A.6, "PUSHBUTTON SMD PTS820 NO HOLES", Color=Black, Manufacturer=C&K, Max Operating Temperature=85°C, Min Operating Temperature=-40°C
PortentaBoardShape_3D_Hirose3.5mm: library part UT0026-A.2
R1 R5 R6 R7 R8 R14 R15 R16 R17: library part R0000-A.5, "RES CHIP 0402 0R 1/16W", Case Code (Imperial)=0402, Case Code (Metric)=1005, Manufacturer=Vishay, Manufacturer 2=Panasonic, Manufacturer Part Number 2=ERJ-S020R00X, Power=63mW, Tolerance=J
R4 R20 R21 R22: library part R0001-A.5, "RES CHIP 0402 100K 1% 1/16W", Case Code (Imperial)=0402, Case Code (Metric)=1005, Manufacturer=Vishay, Manufacturer 2=Panasonic, Manufacturer Part Number 2=ERJ-2RKF1003X, Power=63mW, Tolerance=1%
R18 R19: library part R0055-A.6, "RES CHIP 0402 470R 5% 1/16W", Case Code (Imperial)=0402, Case Code (Metric)=1005, Manufacturer=Vishay, Manufacturer 2=Panasonic, Manufacturer Part Number 2=ERJ-2GEJ471X, Power=63mW, Tolerance=1%
R23: library part R0058-A.5, "RES CHIP 0402 1M 1% 1/16W", Case Code (Imperial)=0402, Case Code (Metric)=1005, Manufacturer=Vishay, Manufacturer 2=Panasonic, Manufacturer Part Number 2=ERJ-2RKF1004X, Power=63mW, Tolerance=1%
S1 S2: library part S0013-A.1, "ROUND STANDOFF M2X0.4 STEEL 3MM", Manufacturer="Würth Elektronik"
SJ1 SJ2: library part UT0006-A.10, "Solder Jumper shorted pads"
SW1: library part S0006-A.5, "Switch DIP normally open", Contact Resistance=100mR, Current Rating=25mA, Manufacturer="CTS Corporation", Max Operating Temperature=85°C, Max Voltage Rating (DC)=24V, Min Operating Temperature=-55°C, Package Quantity=145
TP1: library part UT0014-A.2, "Test point 1.27mm"
U1: library part U0052-A.5, "IC POWER SWITCH DUAL CHANNEL OCP", Manufacturer="ON Semiconductor", Max Input Voltage=5.5V, Max Operating Temperature=85°C, Max Output Current=2.5A, Max Power Dissipation=850mW, Max Supply Current=1uA, Min Input Voltage=2.7V, Min Operating Temperature=-40°C, On-State Resistance=95mR, Package Quantity=3000
USBFS USBHS: library part J0163-A.2

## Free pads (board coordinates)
  round 0 hole 2.54 unplated: 15(2.75,8.4) 15(2.75,63.6) 15(58.102,14.732) 15(105.855,57.404) 15(161.207,8.4) 15(161.207,63.6)

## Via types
v1: diameter 0.6, hole 0.3, Top to Bottom, tented both sides, 387 vias

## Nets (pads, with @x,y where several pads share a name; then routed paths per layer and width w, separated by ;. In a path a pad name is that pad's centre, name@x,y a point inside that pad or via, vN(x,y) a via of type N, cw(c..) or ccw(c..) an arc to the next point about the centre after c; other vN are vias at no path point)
+3V3: GPIO.1 I2C.1 I2C.5 I2C.9 I2S.1 J2.23 J2.34 J2.43 J2.69 J4.2 J4.10 J4.20 J4.30 J4.36 J16.23 J16.34 J16.43 J16.69 JTAG.1 R5.1 R19.2 R22.1 SAI.1 SJ1.2 SJ2.2 SPI0.1 SPI1.1 SW1.1 SW1.2 UART0.1 UART1.1 UART2.1 UART3.1 | length 46.8
  Top w0.19: v1(96.935,30.31) 97.025,30.31 97.393,29.941 97.875,29.941 98.292,29.524 99.726,29.524 99.786,29.464 J2.34@100.57,29.464 ; J2.69@103.65,22.264 104.51,22.264 104.591,22.183 ; J2.23@103.65,31.464 104.701,31.464 104.791,31.374 v1(104.902,31.374)
  Top w0.2: v1(79.964,57.346) 82.176,57.346 82.264,57.434 R5.1@84.038,57.434 ; J2.43@103.65,27.464 106.549,27.464 v1(106.596,27.418) ; 104.591,22.183 104.965,21.809 105.668,21.809 v1(105.713,21.764) ; SW1.1@114.365,32.19 114.376,32.179 114.376,30.945 v1(114.371,30.94) ; v1(115.615,30.97) 115.635,30.991 SW1.2@115.635,32.19
  Top w0.264: R19.2@37.81,19.025 37.814,19.029 38.712,19.029 v1(38.725,19.016) ; v1(70.6,58.736) 70.65,58.686 J4.36@70.65,58.018 ; J4.36@70.65,57.324 70.65,56.267 70.964,55.953 71.977,55.953 72.132,56.108 72.132,57.306 J4.30@72.15,57.324 ; J4.20@74.65,57.324 v1(74.65,58.864)
  Top w0.3: SJ1.2@14.287,25.869 v1(14.287,27.178) ; SJ2.2@18.732,25.869 v1@18.732,27.214 ; v1(54.452,38.983) 54.533,38.983 54.879,39.329 R22.1@56.119,39.329 ; J4.36@70.65,57.324 J4.36@70.65,58.018 ; J4.10@77.15,57.324 77.15,58.517 77.498,58.865 v1(77.498,58.947) ; J4.2@79.15,57.324 79.935,57.324 v1@79.95,57.339
  Top w0.4: JTAG.1@47.774,58.69 v1(47.774,62.351)
  Bottom w0.19: v1(96.935,30.31) 97.025,30.31 97.393,29.941 97.87,29.941 98.282,29.529 98.501,29.529 98.506,29.524 99.75,29.524 99.81,29.464 J16.34@100.83,29.464 ; J16.69@103.41,22.264 104.825,22.264 ; J16.23@103.41,31.464 104.222,31.464 104.282,31.404 104.872,31.404 v1(104.902,31.374)
  Bottom w0.2: J16.43@103.71,27.464 106.549,27.464 v1(106.596,27.418) ; 104.825,22.264 104.925,22.164 104.928,22.164 105.251,21.84 105.636,21.84 v1(105.713,21.764)
  other v1: 18.732,27.305
+5V: CAN0.1 CAN1.1 J1.21 J1.32 J1.41 J1.48 J8.1 J15.21 J15.32 J15.41 J15.48 U1.2 U1.3 | length 32.8
  Top w0.19: v1(56.139,24.17) 56.25,24.17 56.344,24.264 J1.21@57.39,24.264 ; J1.41@57.13,28.264 58.347,28.264 58.727,27.884 v1(58.799,27.884)
  Top w0.2: 54.014,28.264 J1.41@57.13,28.264 ; v1(59.519,29.464) J1.48@60.47,29.464 ; J1.32@60.47,26.264 61.7,26.264 61.845,26.119 v1(61.954,26.119) ; U1.2@61.484,40.358 62.192,40.358 62.309,40.475 ; U1.3@61.484,40.858 62.192,40.858 62.309,40.741 62.309,40.475 ; v1(62.673,40.189) 62.596,40.189 62.309,40.475
  Top w0.8: v1(41.839,30.006) 41.839,29.228 v1(41.85,29.217) 47.348,29.217 47.456,29.325 52.953,29.325 54.014,28.264
  Top w1: CAN0.1@79.92,5.2 CAN1.1@79.92,7.74
  Bottom w0.19: v1(56.139,24.17) 56.205,24.236 56.644,24.236 56.672,24.264 J15.21@57.65,24.264 ; J15.41@57.39,28.264 58.347,28.264 58.727,27.884 v1(58.799,27.884)
  Bottom w0.2: v1(59.519,29.464) J15.48@60.23,29.464 ; J15.32@60.23,26.264 61.7,26.264 61.845,26.119 v1(61.954,26.119)
A0_1: ANALOG.8 J2.73 J16.73 | length 53
  Top w0.19: J2.73@103.65,21.464 104.993,21.464 105.929,20.528 v1(106.983,20.528)
  Top w0.2: v1(106.983,20.528) v1@107.065,20.528 ; v1(107.853,17.514) 107.961,17.514 108.135,17.688 119.178,17.688 120.299,18.809 132.336,18.809 138.671,12.474 138.671,6.449 ANALOG.8@139.98,5.14
  Bottom w0.19: J16.73@103.41,21.464 105.133,21.464 106.069,20.528 v1(106.983,20.528)
  Bottom w0.2: v1(106.983,20.528) 107.853,19.658 v1(107.853,17.514)
A1_1: ANALOG.7 J2.75 J16.75 | length 54.5
  Top w0.2: J2.75@103.65,21.064 104.905,21.064 106.005,19.964 v1@106.469,19.964 ; v1(107.08,17.827) 107.188,17.827 107.425,18.064 117.704,18.064 119.488,19.848 132.856,19.848 141.198,11.506 141.198,6.462 ANALOG.7@142.52,5.14
  Bottom w0.2: J16.75@103.41,21.064 104.919,21.064 105.009,20.974 105.135,20.974 106.171,19.938 106.494,19.938 v1(106.545,19.887) 106.545,18.362 v1(107.08,17.827)
A2_1: ANALOG.6 J2.77 J16.77 | length 58.7
  Top w0.19: J2.77@103.65,20.664 104.655,20.664 104.956,20.363
  Top w0.2: v1(104.702,18.515) 116.796,18.515 119.337,21.056 134.31,21.056 143.754,11.612 143.754,6.446 ANALOG.6@145.06,5.14 ; 104.956,20.363 105.905,19.415 v1(105.963,19.415)
  Bottom w0.19: J16.77@103.41,20.664 104.648,20.664 105.139,20.173 105.139,20.057 105.412,19.784 105.547,19.784 105.916,19.415 v1(105.963,19.415)
  Bottom w0.2: v1(104.702,18.515) 104.779,18.591 105.259,18.591 105.799,19.13 105.799,19.142 105.963,19.306 v1(105.963,19.415)
A3_1: ANALOG.5 J2.79 J16.79 | length 60.9
  Top w0.2: J2.79@103.65,20.264 104.489,20.264 105.022,19.731 v1@105.022,19.448 ; v1(104.767,19.448) v1@105.022,19.448 ; ANALOG.5@147.6,5.14 146.4,6.34 146.4,15.837 139.958,22.279 119.234,22.279 115.82,18.865 105.605,18.865 v1@105.022,19.448
  Bottom w0.2: J16.79@103.41,20.264 104.247,20.264 104.691,19.821 104.691,19.524 v1(104.767,19.448)
A4_1: ANALOG.4 J2.74 J16.74 | length 69.2
  Top w0.2: v1(98.542,21.277) 98.65,21.277 98.904,21.531 99.65,21.531 99.717,21.464 J2.74@100.57,21.464 ; v1(147.887,13.554) 148.97,12.471 148.97,6.137 149.967,5.14 ANALOG.4@150.14,5.14
  Bottom w0.2: J16.74@100.83,21.464 99.801,21.464 99.786,21.479 98.852,21.479 98.65,21.277 v1(98.542,21.277) 98.542,21.169 98.219,20.846 98.219,17.749 102.635,13.333 147.187,13.333 147.331,13.477 147.81,13.477 v1(147.887,13.554)
A5_1: ANALOG.3 J2.76 J16.76 | length 66.9
  Top w0.2: v1(99.284,20.929) 99.361,21.005 99.577,21.005 99.635,21.064 J2.76@100.57,21.064 ; v1(149.071,15.004) 151.339,12.736 151.339,6.481 ANALOG.3@152.68,5.14
  Bottom w0.19: 101.408,21.064 101.525,20.947
  Bottom w0.2: v1(99.284,20.929) 99.361,21.005 99.553,21.005 99.612,21.064 99.995,21.064 J16.76@100.83,21.064 101.408,21.064 ; 101.525,20.947 101.525,18.114 104.827,14.812 148.26,14.812 148.452,15.004 v1(149.071,15.004)
A6_1: ANALOG.2 J2.78 J16.78 | length 71.5
  Top w0.2: v1(98.769,20.347) 98.692,20.271 98.692,19.923 98.685,19.916 98.685,19.013 v1(99.139,18.559) ; v1@98.792,20.347 99.48,20.347 99.797,20.664 J2.78@100.57,20.664 ; v1(152.592,14.104) 154.002,12.694 154.002,6.358 ANALOG.2@155.22,5.14
  Bottom w0.2: v1(98.769,20.347) 99.48,20.347 99.797,20.664 J16.78@100.83,20.664 ; v1(99.139,18.559) 103.594,14.104 v1(152.592,14.104)
A7_1: ANALOG.1 J2.80 J16.80 | length 73.2
  Top w0.2: v1(99.936,18.878) 99.501,19.313 99.501,19.765 100,20.264 J2.80@100.57,20.264
  Bottom w0.2: v1@99.859,18.955 99.859,19.477 99.689,19.647 99.689,20.061 99.892,20.264 J16.80@100.83,20.264 ; v1(99.936,18.878) 99.936,18.77 100.079,18.626 100.079,18.573 104.198,14.454 149.299,14.454 149.499,14.654 153.986,14.654 159.319,9.321 159.319,6.699 ANALOG.1@157.76,5.14
ANALOG.VREF_1_N: ANALOG.10 J2.72 J16.72 | length 46.7
  Top w0.19: J2.72@100.57,21.864 101.76,21.864 101.908,21.716 v1(102.019,21.716)
  Top w0.2: v1(128.474,15.898) 133.41,10.962 133.41,6.63 ANALOG.10@134.9,5.14
  Bottom w0.19: J16.72@100.83,21.864 101.76,21.864 101.908,21.716 v1(102.019,21.716) 102.019,21.605 102.375,21.249 102.375,21.209
  Bottom w0.2: 102.375,21.209 102.375,18.999 105.476,15.898 110.084,15.898 110.434,15.548 111.18,15.548 111.53,15.898 v1(128.474,15.898)
ANALOG.VREF_1_P: ANALOG.9 J2.71 J16.71 | length 49.6
  Top w0.19: v1(103.18,19.184) 103.18,19.295 102.904,19.571 102.904,21.753 103.015,21.864 J2.71@103.65,21.864
  Top w0.2: v1(129.764,16.486) 136.138,10.112 136.138,6.442 ANALOG.9@137.44,5.14
  Bottom w0.19: 102.8,19.639 102.8,19.662 102.765,19.697 102.765,21.718 102.911,21.864 103.079,21.864 J16.71@103.41,21.864
  Bottom w0.2: 102.8,19.639 103.218,19.222 103.218,19.146 106.116,16.248 110.229,16.248 110.579,15.898 111.035,15.898 111.385,16.248 117.924,16.248 118.124,16.448 129.726,16.448 v1(129.764,16.486)
BOOT_1: J2.1 J16.1 SW1.3 | length 24.3
  Top w0.19: J2.1@103.65,35.864 104.362,35.864 105.404,36.906 105.404,38.588 105.511,38.695 105.511,38.725 105.664,38.878 v1(105.664,38.989)
  Top w0.2: SW1.3@115.635,39.81 115.712,39.887 115.712,40.628 116.332,41.248 116.614,41.248 116.914,41.547 v1(117.022,41.547)
  Bottom w0.19: J16.1@103.41,35.864 104.276,35.864 105.403,36.99 105.403,38.673 105.664,38.934 v1(105.664,38.989)
  Bottom w0.2: v1(105.664,38.989) 108.684,42.009 116.56,42.009 v1(117.022,41.547)
BT_SEL_1: J2.3 J16.3 SW1.4 | length 19.9
  Top w0.2: J2.3@103.65,35.464 104.45,35.464 104.533,35.548 104.856,35.548 105.949,36.641 v1(105.949,37.955) ; SW1.4@114.372,39.817 SW1.4@114.365,39.81 114.365,40.695 114.433,40.763 114.738,40.763 v1(114.815,40.84)
  Bottom w0.2: J16.3@103.41,35.464 104.772,35.464 105.949,36.641 v1(105.949,37.955) ; v1@105.957,37.955 105.957,37.963 108.843,40.849 114.806,40.849 v1(114.815,40.84)
CAM.CK_1_N: CAMERA.3 J2.20 J4.14 J16.20 | length 58.4
  Top w0.2: v1(94.221,34.806) 96.668,34.806 97.901,33.573 98.073,33.573 98.871,32.775 99.076,32.775 99.587,32.264 J2.20@100.57,32.264
  Top w0.264: v1@85.156,42.544 86.473,42.544 94.21,34.806 v1(94.221,34.806)
  Top w0.3: v1(76.4,55.525) 76.343,55.582 76.343,55.795 76.168,55.969 76.168,56.238 76.15,56.256 J4.14@76.15,57.324 76.15,58.414 80.378,62.642 80.378,65.422 CAMERA.3@79.02,66.78
  Bottom w0.2: v1(94.221,34.806) 96.602,34.806 97.835,33.573 98.572,33.573 99.146,32.999 99.202,32.999 99.937,32.264 J16.20@100.83,32.264
  Bottom w0.3: v1(76.4,55.525) 76.343,55.468 76.343,55.255 76.292,55.205 76.292,54.957 77.597,53.652 78.148,53.652 82.686,49.115 82.686,48.164 85.577,45.273 85.577,43.046 85.15,42.618 v1@85.15,42.537
  other v1: 85.164,42.544
CAM.CK_1_P: CAMERA.4 J2.18 J4.16 J16.18 | length 55.4
  Top w0.2: v1(94.201,35.606) 96.331,35.606 97.802,34.135 97.974,34.135 99.007,33.102 99.212,33.102 99.65,32.664 J2.18@100.57,32.664
  Top w0.264: v1@84.982,43.298 86.509,43.298 v1(94.201,35.606)
  Top w0.3: v1(75.675,55.577) 75.668,55.584 75.668,56.031 75.65,56.049 J4.16@75.65,57.324 75.65,58.625 79.9,62.875 79.9,63.589 79.249,64.24 CAMERA.4@79.02,64.24
  Bottom w0.2: v1(94.201,35.606) 96.265,35.606 97.969,33.901 98.707,33.901 99.282,33.326 99.337,33.326 99.999,32.664 J16.18@100.83,32.664
  Bottom w0.3: v1(75.675,55.577) 75.675,55.496 75.842,55.329 75.842,54.77 77.41,53.202 77.962,53.202 82.236,48.928 82.236,47.978 85.127,45.086 85.127,43.524 84.976,43.373 v1@84.976,43.292
  other v1: 84.99,43.298
CAM.D0_1_N: CAMERA.11 J2.16 J4.31 J16.16 | length 67.7
  Top w0.2: v1(95.047,36.133) 95.124,36.056 95.453,36.056 95.577,35.933 96.466,35.933 97.873,34.526 98.045,34.526 99.142,33.429 99.347,33.429 99.554,33.222 ; 99.669,33.107 99.712,33.064 J2.16@100.57,33.064
  Top w0.264: CAMERA.11@68.86,66.78 69.115,66.525 69.115,65.872 69.27,65.717 69.288,65.717 70.261,64.744 70.261,62.946 v1@71.793,61.414 ; v1(71.972,45.523) 72.015,45.523 72.294,45.802 72.769,45.802 74.62,43.951 87.229,43.951 v1(95.047,36.133)
  Top w0.3: J4.31@71.65,53.724 71.65,52.924 71.65,51.803 72.002,51.451 72.002,51.203 71.949,51.15 71.949,50.938 v1(71.892,50.88)
  Bottom w0.2: v1(95.047,36.133) 95.124,36.056 95.453,36.056 95.577,35.933 96.4,35.933 98.105,34.228 98.842,34.228 99.417,33.653 99.472,33.653 100.061,33.064 J16.16@100.83,33.064
  Bottom w0.264: v1@71.793,61.414 71.743,61.364 71.743,61.006 71.349,60.612 71.349,60.137 71.334,60.122 71.334,51.995 71.357,51.973 71.357,51.735 71.827,51.264 71.827,50.945 v1(71.892,50.88) 71.892,49.834 70.859,48.801 70.859,46.634 71.969,45.523 v1(71.972,45.523)
  other v1: 71.807,61.421
CAM.D0_1_P: CAMERA.12 J2.14 J4.29 J16.14 | length 64
  Top w0.2: v1(95.795,36.46) 95.903,36.46 96.103,36.26 96.602,36.26 97.938,34.924 98.256,34.924 99.424,33.756 99.483,33.756 99.775,33.464 J2.14@100.57,33.464
  Top w0.264: CAMERA.12@68.86,64.24 69.87,63.23 69.87,62.784 71.234,61.42 71.234,61.183 71.927,60.489 v1@72.009,60.489 ; v1(71.842,46.441) 71.932,46.441 72.157,46.216 72.941,46.216 74.698,44.459 87.681,44.459 95.536,36.604 95.56,36.604 95.704,36.46 v1(95.795,36.46)
  Top w0.3: J4.29@72.15,53.724 72.15,52.01 72.502,51.658 72.502,51.079 72.675,50.906 v1(72.675,50.825)
  Bottom w0.2: v1(95.795,36.46) 95.903,36.46 96.103,36.26 96.535,36.26 98.24,34.555 98.978,34.555 99.553,33.98 99.608,33.98 100.124,33.464 J16.14@100.83,33.464
  Bottom w0.264: v1(71.842,46.441) 71.842,46.532 71.3,47.074 71.3,48.55 72.3,49.55 ; v1@72.009,60.489 72.009,60.442 71.74,60.173 71.74,59.975 71.725,59.96 71.725,52.157 72.387,51.496 72.387,51.204 72.675,50.916 v1(72.675,50.825)
  Bottom w0.3: 72.3,49.55 72.675,49.925 v1(72.675,50.825)
  other v1: 72.023,60.496
CAM.D1_1_N: CAMERA.9 J2.12 J4.35 J16.12 | length 67.7
  Top w0.2: v1(96.41,36.848) 96.476,36.848 98.006,35.318 98.324,35.318 99.559,34.083 99.618,34.083 99.837,33.864 J2.12@100.57,33.864
  Top w0.264: v1@68.825,51.139 68.825,51.048 69.025,50.848 69.025,50.481 72.251,47.255 72.455,47.255 74.86,44.85 88.468,44.85 96.41,36.908 v1(96.41,36.848) ; v1@69.375,58.789 69.375,56.989 70.65,55.714 J4.35@70.65,53.724
  Bottom w0.2: v1(96.41,36.848) 98.376,34.882 99.113,34.882 99.688,34.307 99.743,34.307 100.186,33.864 J16.12@100.83,33.864
  Bottom w0.264: v1@68.825,51.139 68.825,51.23 68.978,51.383 68.978,53.271 68.643,53.606 68.643,54.414 69.634,55.405 69.634,58.467 69.375,58.725 69.375,58.789 69.439,58.853 69.439,60.345 70.246,61.152 70.246,64.584 71.4,65.738 CAMERA.9@71.4,66.78
  other v1: 68.839,51.146 69.389,58.796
